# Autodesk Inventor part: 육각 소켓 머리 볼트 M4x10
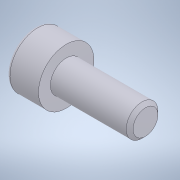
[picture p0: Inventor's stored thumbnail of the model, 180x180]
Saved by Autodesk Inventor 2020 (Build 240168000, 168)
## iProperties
Created: 2024-04
Part Number: 육각 소켓 머리 볼트 M4x10
Material: 강철, 연강
Description: 6각머리 태핑 나사
Document SubType Name: Modeling
Designer: oem
Density: 7.86 g/cm^3
Appearance: 기본값
Author: jhkim
Sending System: Autodesk Inventor 2025
Preprocessor: ST-DEVELOPER v20
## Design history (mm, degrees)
feature "Solid1"
node "솔리드1"
